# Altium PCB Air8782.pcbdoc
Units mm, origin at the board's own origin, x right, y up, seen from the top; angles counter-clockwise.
Board outline 40.95 x 43.9 mm, 2 copper layers (Top Layer, Bottom Layer); 1 components, 0 nets, 20 pads, 0 vias.
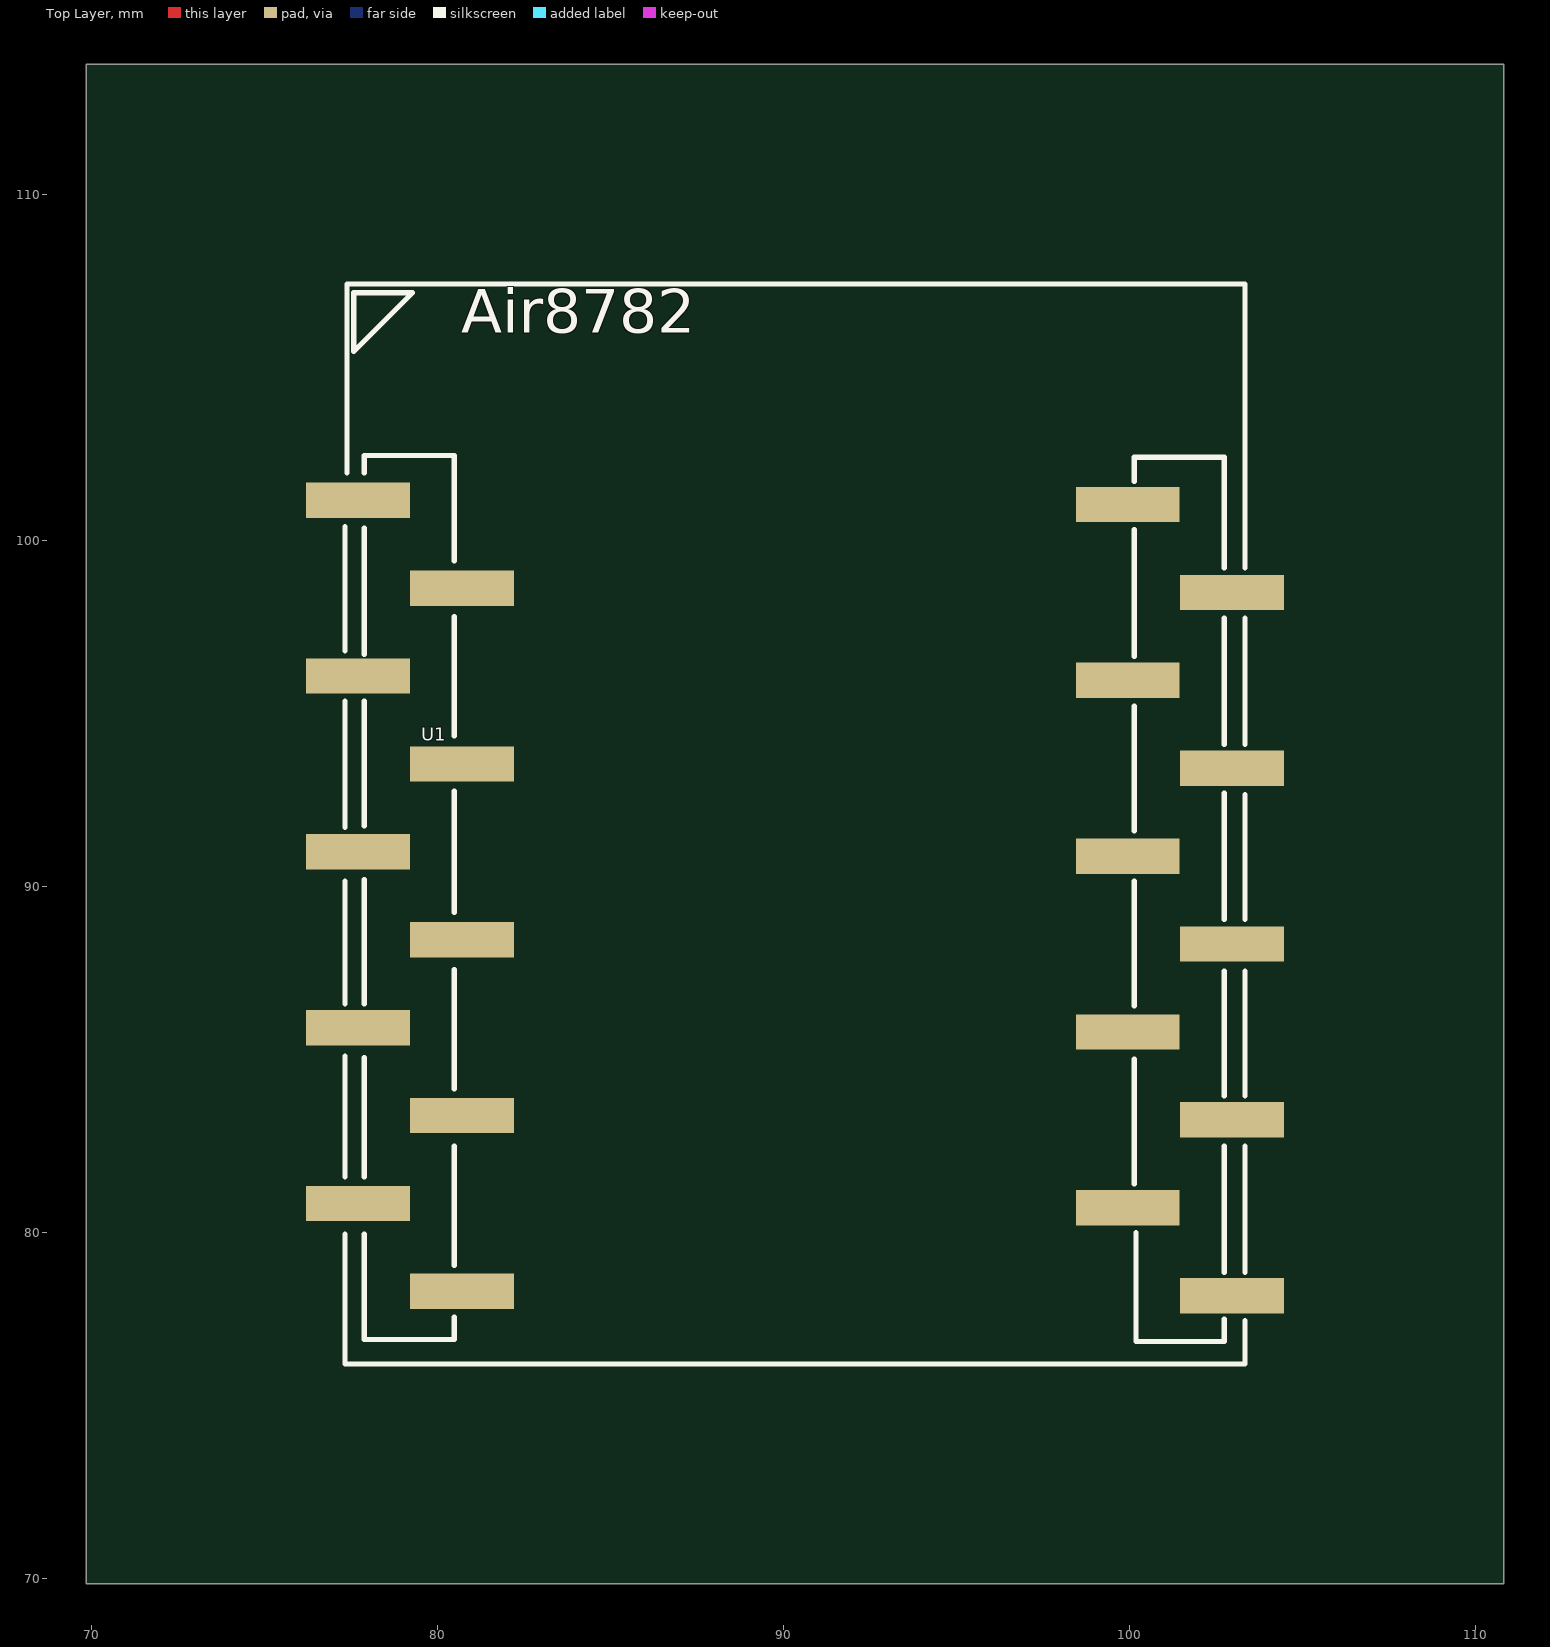
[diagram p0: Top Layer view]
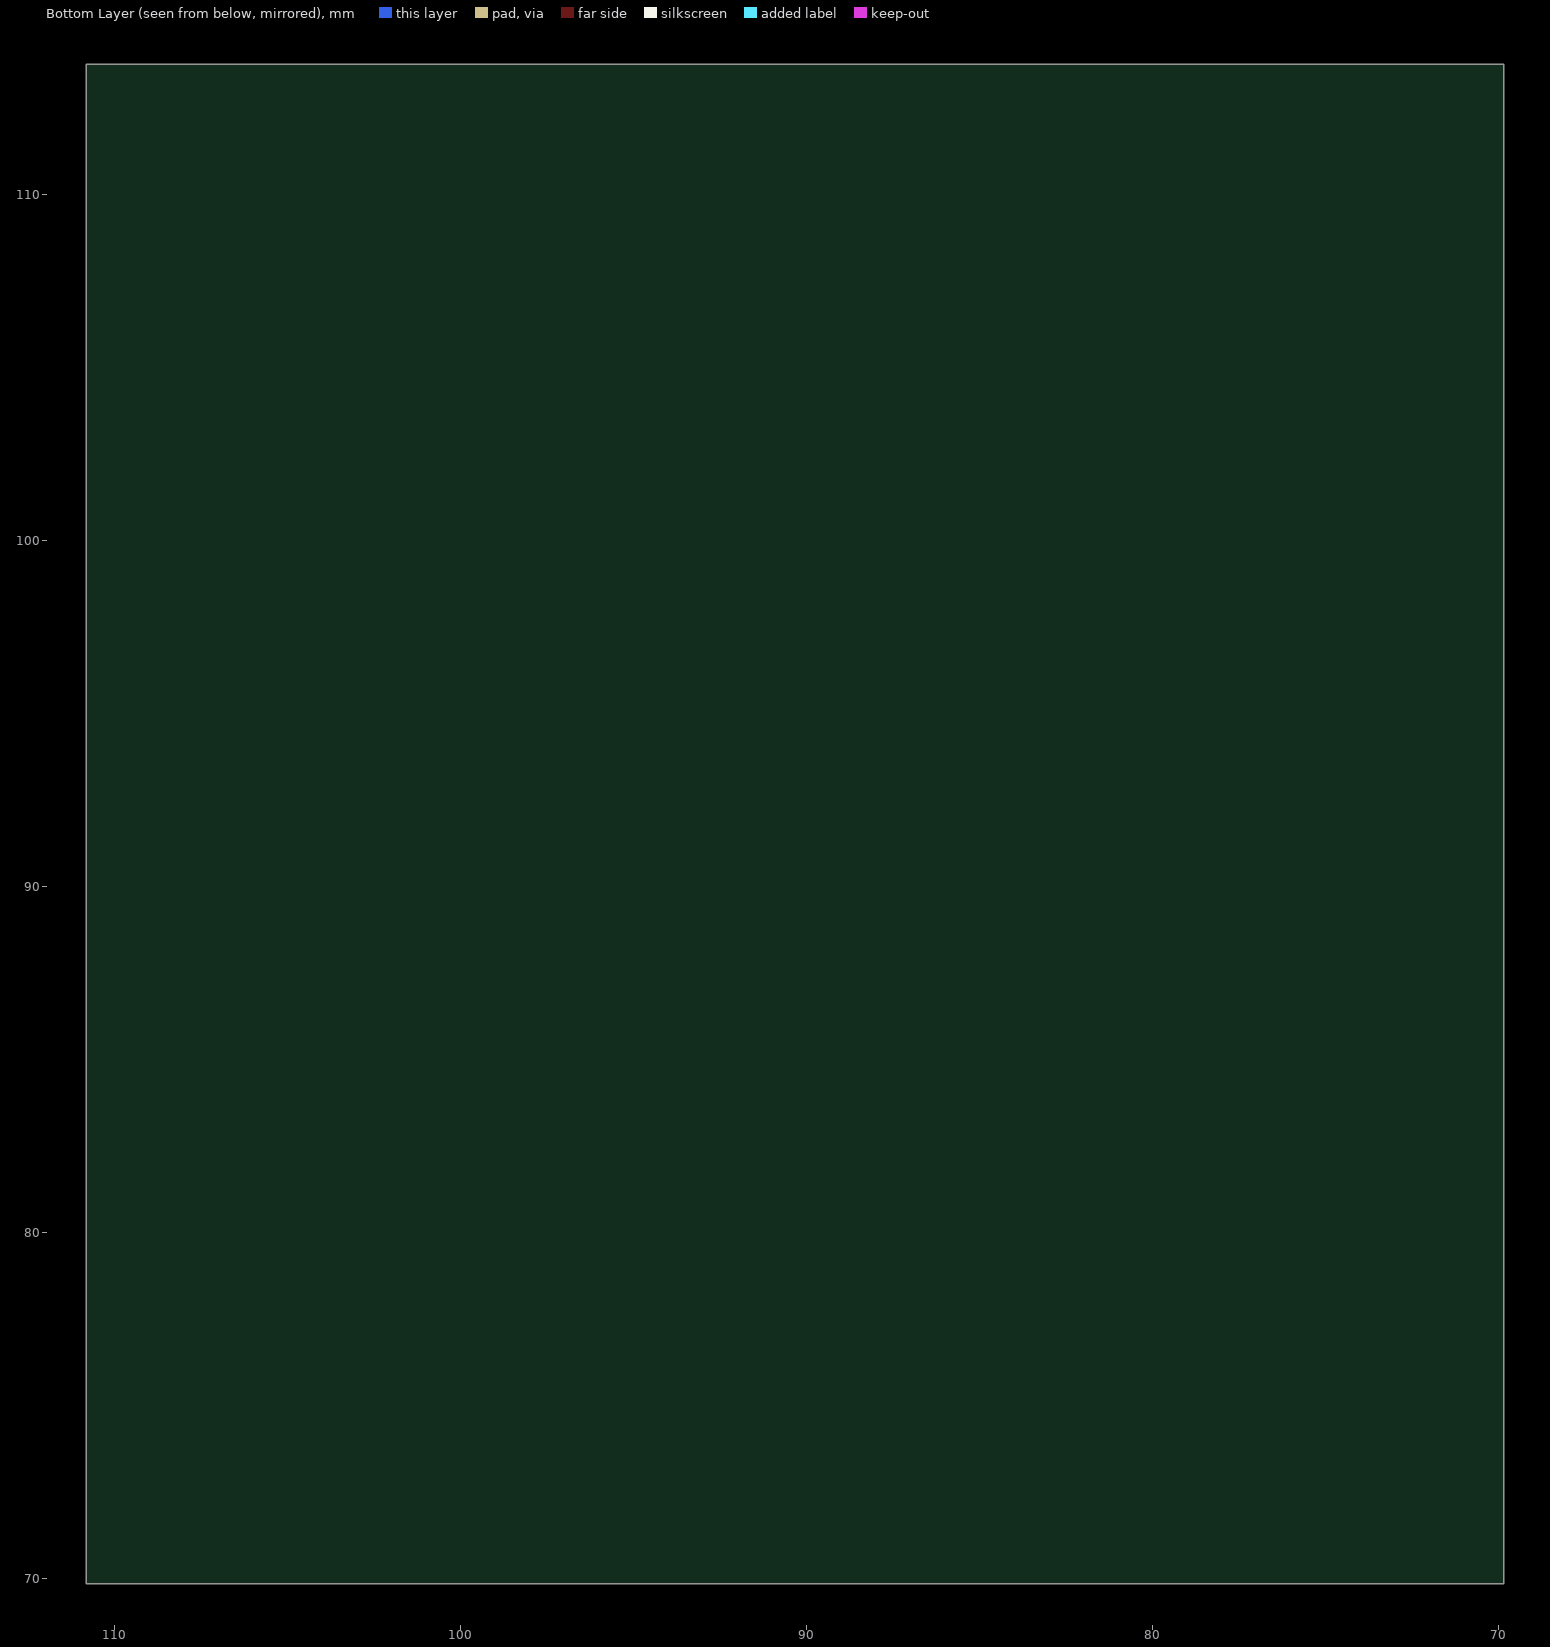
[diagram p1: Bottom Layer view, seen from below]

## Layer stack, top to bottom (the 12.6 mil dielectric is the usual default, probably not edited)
Top Layer: signal copper (thickness not stored)
Dielectric: dielectric 0.32, FR-4, Dk 4.8
Bottom Layer: signal copper (thickness not stored)

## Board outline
110.802,69.85 69.85,69.85 69.85,113.75 110.802,113.75

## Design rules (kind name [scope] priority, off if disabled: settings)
BoardOutlineClearance safeClearance [All] p0: genericclearance=0.254 ignorepadtopadclearanceinfootprint=FALSE except(0: Region-OutlineEdge Poly-OutlineEdge Text-OutlineEdge Sheet-OutlineEdge Hole-OutlineEdge Track-CutoutEdge SMDPad-CutoutEdge THPad-CutoutEdge Via-CutoutEdge Fill-CutoutEdge Region-CutoutEdge Poly-CutoutEdge Text-CutoutEdge Sheet-CutoutEdge Hole-CutoutEdge Arc-SplitContinuation Track-SplitContinuation SMDPad-SplitContinuation THPad-SplitContinuation Via-SplitContinuation Fill-SplitContinuation Poly-SplitContinuation Region-SplitContinuation Text-SplitContinuation; 0.152: Track-OutlineEdge SMDPad-OutlineEdge THPad-OutlineEdge Via-OutlineEdge Fill-OutlineEdge)
Clearance safeClearance [All] p1: gap=0.178 ignorepadtopadclearanceinfootprint=FALSE except(0: Region-Track Poly-Track Region-SMDPad Poly-SMDPad Region-THPad Poly-THPad Region-Via Poly-Via Region-Fill Poly-Fill Text-Fill Track-Region SMDPad-Region THPad-Region Via-Region Fill-Region Region-Region Poly-Region Text-Region Sheet-Region Hole-Region Track-Poly SMDPad-Poly THPad-Poly Via-Poly Fill-Poly Region-Poly Poly-Poly Text-Poly Sheet-Poly Hole-Poly Fill-Text Region-Text Poly-Text Text-Text Sheet-Text Hole-Text Region-Sheet Poly-Sheet Text-Sheet Sheet-Sheet Hole-Sheet Region-Hole Poly-Hole Text-Hole Sheet-Hole; 0.152: Track-Track SMDPad-Track THPad-Track Via-Track Fill-Track Text-Track Sheet-Track Hole-Track Track-SMDPad SMDPad-SMDPad THPad-SMDPad Via-SMDPad Fill-SMDPad Text-SMDPad Sheet-SMDPad Hole-SMDPad Track-THPad SMDPad-THPad THPad-THPad Via-THPad Fill-THPad Text-THPad Sheet-THPad Hole-THPad Track-Via SMDPad-Via THPad-Via Via-Via Fill-Via Text-Via Sheet-Via Hole-Via Track-Fill SMDPad-Fill THPad-Fill Via-Fill Fill-Fill Sheet-Fill Hole-Fill Track-Text SMDPad-Text THPad-Text Via-Text Track-Sheet SMDPad-Sheet THPad-Sheet Via-Sheet Fill-Sheet Track-Hole SMDPad-Hole THPad-Hole Via-Hole Fill-Hole Hole-Hole)
PasteMaskExpansion Common [All] p1: expansion=0
SolderMaskExpansion Common [All] p1: useseparateexpansions=TRUE expansion=0 expansionbottom=0
Width trackWidth [All] p1: maxlimit=12 minlimit=12 preferedwidth=12

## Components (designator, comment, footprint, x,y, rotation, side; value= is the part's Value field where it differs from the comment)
U1 "AIR8782" AIR8782 77.328,76.2 r0 top

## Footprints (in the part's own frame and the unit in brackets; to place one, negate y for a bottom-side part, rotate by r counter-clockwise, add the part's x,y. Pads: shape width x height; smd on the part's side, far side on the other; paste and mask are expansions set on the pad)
AIR8782 [mm]
  rect 3x1.02 smd: 1(0.372,24.955) 2(3.372,22.415) 3(0.372,19.875) 4(3.372,17.335) 5(0.372,14.795) 6(3.372,12.255) 7(0.372,9.715) 8(3.372,7.175) 9(0.372,4.635) 10(3.372,2.095) 11(25.625,1.971) 12(22.615,4.511) 13(25.625,7.051) 14(22.615,9.591) 15(25.625,12.131) 16(22.615,14.671) 17(25.625,17.211) 18(22.615,19.751) 19(25.625,22.291) 20(22.615,24.831)
  silkscreen extent 0,0 26,31.2

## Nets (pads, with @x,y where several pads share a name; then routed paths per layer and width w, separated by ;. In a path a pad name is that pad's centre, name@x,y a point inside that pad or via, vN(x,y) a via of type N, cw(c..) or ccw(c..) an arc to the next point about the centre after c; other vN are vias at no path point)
pads on no net: U1.1 U1.2 U1.3 U1.4 U1.5 U1.6 U1.7 U1.8 U1.9 U1.10 U1.11 U1.12 U1.13 U1.14 U1.15 U1.16 U1.17 U1.18 U1.19 U1.20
